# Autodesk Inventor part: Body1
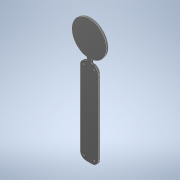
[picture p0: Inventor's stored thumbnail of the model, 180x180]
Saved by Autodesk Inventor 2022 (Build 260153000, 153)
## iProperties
Created: 2022-02
Part Number: Body1
Material: PVC-Piping
Document SubType Name: Modeling
Designer: joshw
Density: 1.4 g/cm^3
Appearance: Smooth - Black
Author: joshw
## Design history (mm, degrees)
sketch "Sketch2"
  geometry: L1 (-4.702, 28.233)-(-5.337, 28.233) reference; L2 (-5.337, 28.233)-(-5.337, 26.328); L3 (-4.702, 26.328)-(-4.702, 28.233); L4 (-5.337, 26.328)-(-4.702, 26.328) reference; L5 (-4.577, 26.963)-(-5.463, 26.963); L6 (-3.688, 15.152)-(-3.688, 26.074); L7 (-5.463, 14.263)-(-4.577, 14.263); L8 (-6.352, 26.074)-(-6.352, 15.152); L9 (-6.352, 14.263)-(-3.688, 26.963); L10 (-3.688, 14.263)-(-6.352, 26.963); L11 (-5.337, 26.328)-(-4.702, 28.233); L12 (-4.702, 26.328)-(-5.337, 28.233); L13 (-5.463, 26.074)-(-6.092, 26.702); L14 (-5.02, 20.613)-(-3.948, 20.613); L15 (-3.948, 20.613)-(-5.02, 20.613); L16 (-5.02, 20.613)-(-5.02, 22.413); C1 r 2.54 at (-5.02, 30.011); C2 r 0.064 at (-5.777, 26.388); C3 r 0.064 at (-4.262, 26.388); C4 r 0.064 at (-5.777, 14.837); C5 r 0.064 at (-4.262, 14.837); A1 r 0.889 centre (-5.463, 26.074) between (-5.463, 26.963) and (-6.352, 26.074); A2 r 0.889 centre (-4.577, 26.074) between (-3.688, 26.074) and (-4.577, 26.963); A3 r 0.889 centre (-4.577, 15.152) between (-4.577, 14.263) and (-3.688, 15.152); A4 r 0.889 centre (-5.463, 15.152) between (-6.352, 15.152) and (-5.463, 14.263); 5 further points
  constraints: 32 end point, 9 centre point, 9 point on circle, 3 horizontal, 3 symmetric about line, 2 midpoint, 1 collinear, 1 vertical, 23 other
  dimensions: "d7" = 5.08 diameter of C1; "d8" = 3.048 distance from line of L5 C1.centre; "d9" = 0.127 diameter of C2; "d10" = 0.4445 distance of C2.centre L13.start
extrude "Extrusion1" new body sketch "Sketch2" stored distance "d5" = 0.254; taper "d6" = 0 deg
body "Solid1"
